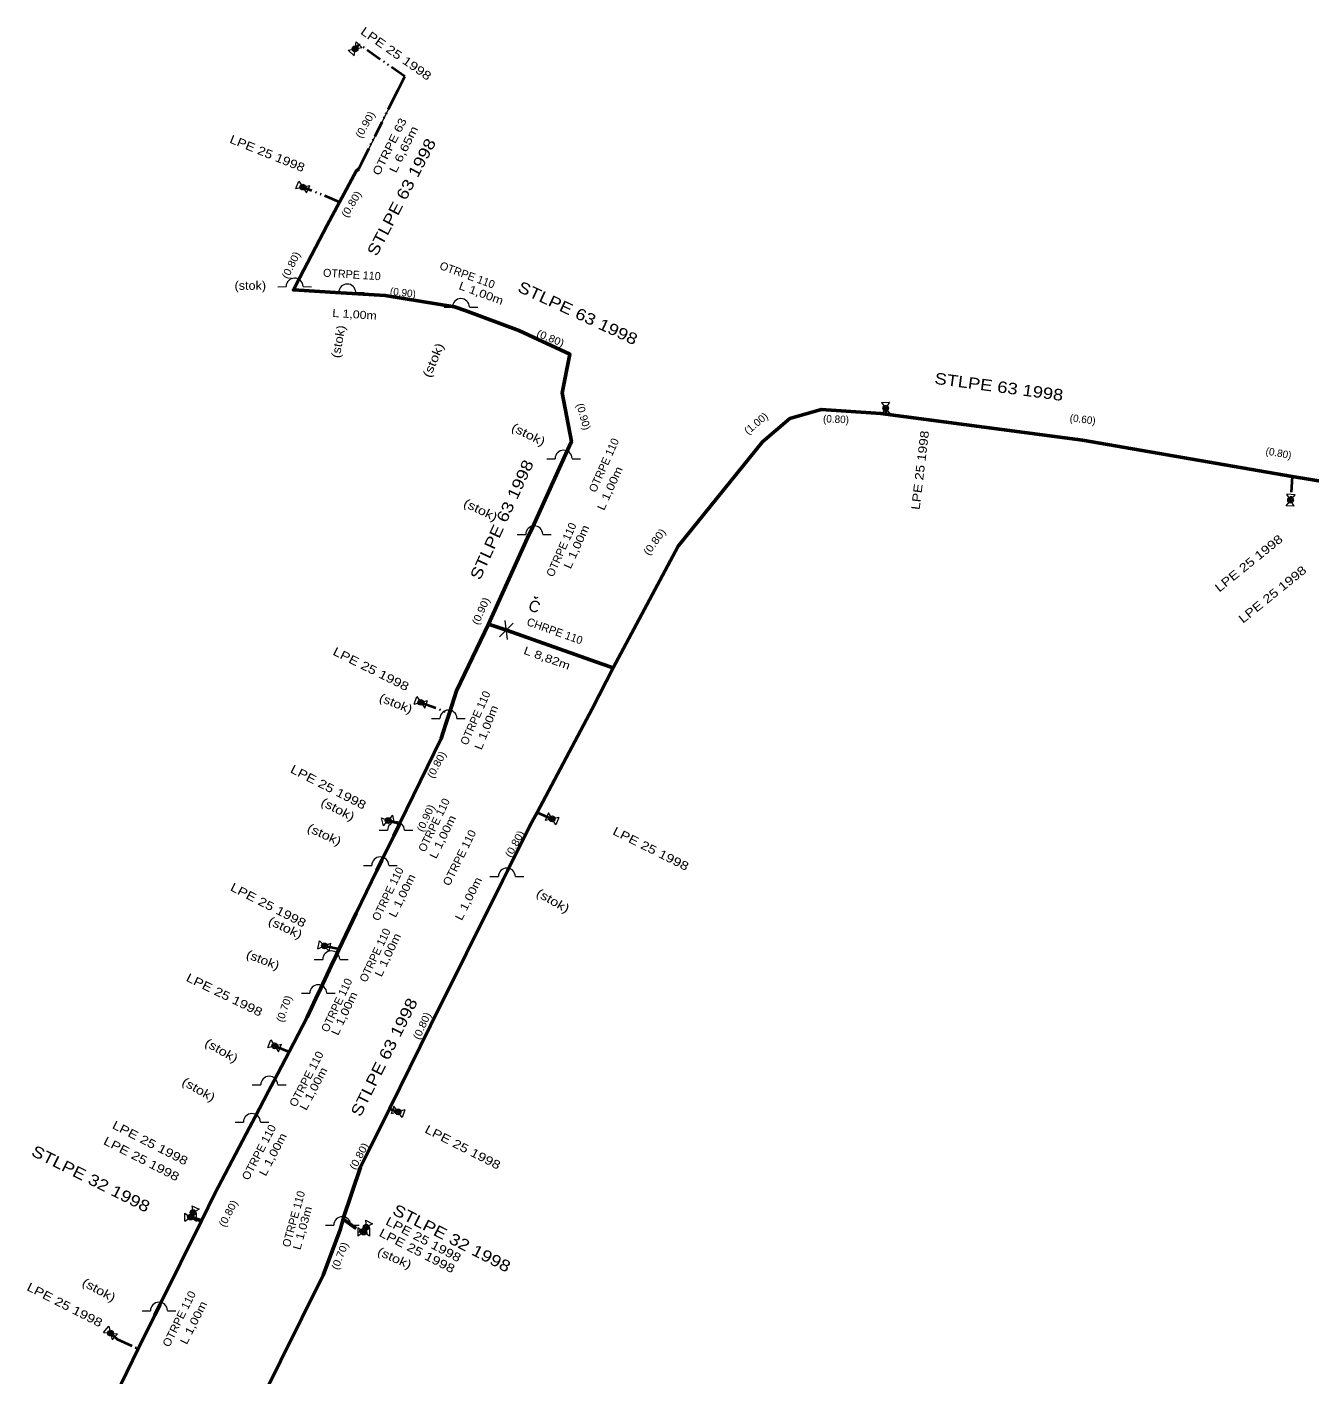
# Model space of a CAD drawing. Extents: x -648036 to -642998, y -1161549 to -1158141.
# Drawn here: x -646651.4 to -646539.3, y -1161084.6 to -1160966.8 of the extents above; entities that cross this region are included whole.
import ezdxf
from ezdxf.enums import TextEntityAlignment as Align

# ---------------------------------------------------------------- set-up
doc = ezdxf.new("R2010")
doc.units = 0
doc.header["$LTSCALE"] = 0.28
doc.linetypes.add('DASH_DOUBLE_DOT', pattern=[9.2, 5, -1.2, 0.3, -1.2, 0.3, -1.2])
for name, color, linetype, lineweight in [('12', 7, 'DASH_DOUBLE_DOT', 40), ('14', 7, 'Continuous', 13), ('15', 7, 'Continuous', 13), ('19', 7, 'Continuous', 13), ('8', 7, 'Continuous', 53)]:
    doc.layers.add(name, color=color, linetype=linetype, lineweight=lineweight)
for name, color, linetype in [('20', 7, 'Continuous'), ('22', 7, 'Continuous'), ('24', 7, 'Continuous'), ('27', 7, 'Continuous'), ('28', 7, 'Continuous')]:
    doc.layers.add(name, color=color, linetype=linetype)

msp = doc.modelspace()

# ---------------------------------------------------------------- linework, layer by layer
at = {"layer": '12'}
for p, q in [((-646624.02, -1160982.11), (-646627.24, -1160980.8)), ((-646576.27, -1161000.14), (-646576.25, -1161000.68)), ((-646540.72, -1161006.11), (-646540.87, -1161008.2)), ((-646616.92, -1161025.88), (-646614.42, -1161026.81)), ((-646606.76, -1161035.51), (-646605.44, -1161036.07)), ((-646625.35, -1161047.19), (-646624.05, -1161047.45)), ((-646629.7, -1161055.93), (-646628.44, -1161056.44)), ((-646619.67, -1161061.45), (-646618.91, -1161061.71)), ((-646637.03, -1161070.91), (-646637.05, -1161070.91)), ((-646637.03, -1161070.91), (-646636.84, -1161070.52)), ((-646621.94, -1161072.22), (-646621.7, -1161071.78)), ((-646621.94, -1161072.22), (-646621.92, -1161072.22))]:
    msp.add_line(p, q, dxfattribs=at)
for points in [[(-646622.35, -1160979.21), (-646622.08, -1160978.67), (-646619.12, -1160972.72), (-646618.93, -1160972.34), (-646618.33, -1160971.13), (-646622.31, -1160968.33), (-646622.67, -1160968.71)], [(-646619.78, -1161036.22), (-646619.65, -1161036.19), (-646618.79, -1161036.52)], [(-646644.05, -1161081.06), (-646643.46, -1161081.58), (-646641.63, -1161082.43)]]:
    msp.add_lwpolyline(points, dxfattribs=at)
at = {"layer": '14'}
for p, q in [((-646619.12, -1160972.72), (-646622.08, -1160978.67)), ((-646627.49, -1160988.72), (-646628.06, -1160989.8)), ((-646623.92, -1160990.05), (-646622.92, -1160990.11)), ((-646613.05, -1160991.61), (-646613.98, -1160991.27)), ((-646604.24, -1161004.13), (-646604.65, -1161005.04)), ((-646607.16, -1161010.57), (-646607.58, -1161011.48)), ((-646609.44, -1161019.56), (-646601.13, -1161022.52)), ((-646614.73, -1161027.76), (-646614.42, -1161026.81)), ((-646619.29, -1161037.55), (-646618.85, -1161036.66)), ((-646620.76, -1161040.58), (-646620.32, -1161039.68)), ((-646609.78, -1161041.5), (-646609.33, -1161040.61)), ((-646624.75, -1161048.94), (-646624.33, -1161048.04)), ((-646626.1, -1161051.79), (-646625.67, -1161050.89)), ((-646629.78, -1161059.01), (-646630.24, -1161059.9)), ((-646631.44, -1161062.19), (-646631.9, -1161063.07)), ((-646623.7, -1161071.03), (-646623.97, -1161072.02)), ((-646640.19, -1161079.5), (-646639.75, -1161078.6))]:
    msp.add_line(p, q, dxfattribs=at)
at = {"layer": '15'}
for p, q in [((-646622.758, -1160969.321), (-646622.582, -1160968.099)), ((-646622.066, -1160968.59), (-646622.582, -1160968.099)), ((-646623.275, -1160968.831), (-646622.066, -1160968.59)), ((-646622.758, -1160969.321), (-646623.275, -1160968.831)), ((-646627.841, -1160980.94), (-646627.573, -1160980.28)), ((-646627.841, -1160980.94), (-646626.639, -1160980.66)), ((-646627.573, -1160980.28), (-646626.908, -1160981.319)), ((-646626.908, -1160981.319), (-646626.639, -1160980.66)), ((-646629.435, -1160989.515), (-646628.7, -1160989.514)), ((-646627.214, -1160989.514), (-646626.48, -1160989.515)), ((-646624.835, -1160990.025), (-646624.1, -1160990.024)), ((-646622.614, -1160990.024), (-646621.88, -1160990.025)), ((-646614.885, -1160991.305), (-646614.15, -1160991.304)), ((-646612.664, -1160991.304), (-646611.93, -1160991.305)), ((-646576.644, -1160999.65), (-646575.933, -1160999.623)), ((-646576.644, -1160999.65), (-646575.896, -1161000.63)), ((-646575.933, -1160999.623), (-646576.607, -1161000.656)), ((-646576.607, -1161000.656), (-646575.896, -1161000.63)), ((-646605.915, -1161004.565), (-646605.18, -1161004.564)), ((-646603.694, -1161004.564), (-646602.96, -1161004.565)), ((-646541.261, -1161008.677), (-646540.479, -1161007.724)), ((-646540.479, -1161007.724), (-646541.189, -1161007.672)), ((-646540.551, -1161008.728), (-646541.189, -1161007.672)), ((-646540.551, -1161008.728), (-646541.261, -1161008.677)), ((-646608.485, -1161011.185), (-646607.75, -1161011.184)), ((-646606.264, -1161011.184), (-646605.53, -1161011.185)), ((-646606.999, -1161016.608), (-646606.904, -1161016.808)), ((-646606.7, -1161016.721), (-646606.904, -1161016.808)), ((-646610.032, -1161020.155), (-646608.849, -1161018.966)), ((-646609.326, -1161020.391), (-646609.555, -1161018.73)), ((-646617.516, -1161026.038), (-646617.268, -1161025.371)), ((-646617.516, -1161026.038), (-646616.324, -1161025.722)), ((-646617.268, -1161025.371), (-646616.573, -1161026.389)), ((-646616.573, -1161026.389), (-646616.324, -1161025.722)), ((-646615.985, -1161027.295), (-646615.25, -1161027.294)), ((-646613.764, -1161027.294), (-646613.03, -1161027.295)), ((-646605.764, -1161035.546), (-646606.043, -1161036.201)), ((-646605.115, -1161036.595), (-646605.764, -1161035.546)), ((-646620.351, -1161035.986), (-646619.21, -1161036.454)), ((-646620.191, -1161036.68), (-646620.351, -1161035.986)), ((-646620.191, -1161036.68), (-646619.369, -1161035.76)), ((-646619.21, -1161036.454), (-646619.369, -1161035.76)), ((-646604.837, -1161035.939), (-646606.043, -1161036.201)), ((-646604.837, -1161035.939), (-646605.115, -1161036.595)), ((-646620.565, -1161037.075), (-646619.83, -1161037.074)), ((-646618.344, -1161037.074), (-646617.61, -1161037.075)), ((-646621.945, -1161040.145), (-646621.21, -1161040.144)), ((-646619.724, -1161040.144), (-646618.99, -1161040.145)), ((-646610.875, -1161041.125), (-646610.14, -1161041.124)), ((-646608.654, -1161041.124), (-646607.92, -1161041.125)), ((-646625.914, -1161047.44), (-646625.774, -1161046.742)), ((-646625.914, -1161047.44), (-646624.786, -1161046.94)), ((-646625.774, -1161046.742), (-646624.927, -1161047.638)), ((-646624.927, -1161047.638), (-646624.786, -1161046.94)), ((-646626.235, -1161048.365), (-646625.5, -1161048.364)), ((-646624.014, -1161048.364), (-646623.28, -1161048.365)), ((-646627.365, -1161051.325), (-646626.63, -1161051.324)), ((-646625.144, -1161051.324), (-646624.41, -1161051.325)), ((-646630.301, -1161056.071), (-646630.034, -1161055.411)), ((-646630.034, -1161055.411), (-646629.367, -1161056.449)), ((-646630.301, -1161056.071), (-646629.099, -1161055.789)), ((-646629.367, -1161056.449), (-646629.099, -1161055.789)), ((-646631.655, -1161059.335), (-646630.92, -1161059.334)), ((-646629.434, -1161059.334), (-646628.7, -1161059.335)), ((-646619.271, -1161061.21), (-646619.502, -1161061.884)), ((-646618.318, -1161061.536), (-646619.502, -1161061.884)), ((-646618.548, -1161062.21), (-646619.271, -1161061.21)), ((-646618.318, -1161061.536), (-646618.548, -1161062.21)), ((-646633.165, -1161062.595), (-646632.43, -1161062.594)), ((-646630.944, -1161062.594), (-646630.21, -1161062.595)), ((-646637.554, -1161071.266), (-646636.546, -1161070.554)), ((-646637.554, -1161070.554), (-646636.547, -1161071.266)), ((-646637.554, -1161071.266), (-646637.554, -1161070.554)), ((-646636.299, -1161070.223), (-646637.38, -1161070.816)), ((-646637.38, -1161070.816), (-646636.741, -1161071.129)), ((-646636.939, -1161069.911), (-646636.741, -1161071.129)), ((-646636.939, -1161069.911), (-646636.299, -1161070.223)), ((-646636.547, -1161071.266), (-646636.546, -1161070.554)), ((-646625.265, -1161071.615), (-646624.53, -1161071.614)), ((-646623.044, -1161071.614), (-646622.31, -1161071.615)), ((-646622.423, -1161071.864), (-646622.424, -1161072.576)), ((-646621.416, -1161071.864), (-646622.424, -1161072.576)), ((-646621.416, -1161072.576), (-646622.423, -1161071.864)), ((-646621.146, -1161071.508), (-646622.253, -1161072.051)), ((-646622.253, -1161072.051), (-646621.629, -1161072.393)), ((-646621.771, -1161071.167), (-646621.629, -1161072.393)), ((-646621.771, -1161071.167), (-646621.146, -1161071.508)), ((-646621.416, -1161071.864), (-646621.416, -1161072.576)), ((-646641.295, -1161079.105), (-646640.56, -1161079.104)), ((-646639.074, -1161079.104), (-646638.34, -1161079.105)), ((-646644.663, -1161080.994), (-646644.193, -1161080.46)), ((-646644.663, -1161080.994), (-646643.437, -1161081.126)), ((-646644.193, -1161080.46), (-646643.908, -1161081.66)), ((-646643.908, -1161081.66), (-646643.437, -1161081.126))]:
    msp.add_line(p, q, dxfattribs=at)
for centre in [(-646627.9574, -1160989.5146), (-646623.3574, -1160990.0246), (-646613.4074, -1160991.3046), (-646604.4374, -1161004.5646), (-646607.0074, -1161011.1846), (-646614.5074, -1161027.2946), (-646619.0874, -1161037.0746), (-646620.4674, -1161040.1446), (-646609.3974, -1161041.1246), (-646624.7574, -1161048.3646), (-646625.8874, -1161051.3246), (-646630.1774, -1161059.3346), (-646631.6874, -1161062.5946), (-646623.7874, -1161071.6146), (-646639.8174, -1161079.1046)]:
    msp.add_arc(centre, 0.7431, 1.2748, 179.83951, dxfattribs=at)
at = {"layer": '19'}
for centre, radius in [((-646622.67, -1160968.71), 0.25), ((-646622.67, -1160968.71), 0.17), ((-646622.67, -1160968.71), 0.09), ((-646627.24, -1160980.8), 0.25), ((-646627.24, -1160980.8), 0.17), ((-646627.24, -1160980.8), 0.09), ((-646576.27, -1161000.14), 0.25), ((-646576.27, -1161000.14), 0.17), ((-646576.27, -1161000.14), 0.09), ((-646540.87, -1161008.2), 0.25), ((-646540.87, -1161008.2), 0.17), ((-646540.87, -1161008.2), 0.09), ((-646616.92, -1161025.88), 0.25), ((-646616.92, -1161025.88), 0.17), ((-646616.92, -1161025.88), 0.09), ((-646619.78, -1161036.22), 0.25), ((-646619.78, -1161036.22), 0.17), ((-646619.78, -1161036.22), 0.09), ((-646605.44, -1161036.07), 0.25), ((-646605.44, -1161036.07), 0.17), ((-646605.44, -1161036.07), 0.09), ((-646625.35, -1161047.19), 0.25), ((-646625.35, -1161047.19), 0.17), ((-646625.35, -1161047.19), 0.09), ((-646629.7, -1161055.93), 0.25), ((-646629.7, -1161055.93), 0.17), ((-646629.7, -1161055.93), 0.09), ((-646618.91, -1161061.71), 0.25), ((-646618.91, -1161061.71), 0.17), ((-646618.91, -1161061.71), 0.09), ((-646637.05, -1161070.91), 0.25), ((-646637.05, -1161070.91), 0.17), ((-646637.05, -1161070.91), 0.09), ((-646636.84, -1161070.52), 0.25), ((-646636.84, -1161070.52), 0.17), ((-646636.84, -1161070.52), 0.09), ((-646621.92, -1161072.22), 0.25), ((-646621.92, -1161072.22), 0.17), ((-646621.92, -1161072.22), 0.09), ((-646621.7, -1161071.78), 0.25), ((-646621.7, -1161071.78), 0.17), ((-646621.7, -1161071.78), 0.09), ((-646644.05, -1161081.06), 0.25), ((-646644.05, -1161081.06), 0.17), ((-646644.05, -1161081.06), 0.09)]:
    msp.add_circle(centre, radius, dxfattribs=at)
at = {"layer": '8', "linetype": 'DASH_DOUBLE_DOT'}
msp.add_line((-646636.11, -1161071.25), (-646637.03, -1161070.91), dxfattribs=at)
at = {"layer": '8'}
for points in [[(-646624.02, -1160982.11), (-646622.56, -1160979.4), (-646622.35, -1160979.21)], [(-646611, -1161019.03), (-646607.58, -1161011.48), (-646607.16, -1161010.57), (-646604.65, -1161005.04), (-646604.24, -1161004.13), (-646603.75, -1161003.05), (-646604.55, -1160998.8), (-646603.88, -1160995.42), (-646608.34, -1160993.35), (-646613.05, -1160991.61), (-646613.98, -1160991.27), (-646620.04, -1160990.29), (-646622.92, -1160990.11), (-646623.92, -1160990.05), (-646628.06, -1160989.8), (-646627.49, -1160988.72), (-646625.1, -1160984.13), (-646624.02, -1160982.11)], [(-646576.25, -1161000.68), (-646576.7, -1161000.62), (-646581.91, -1161000.26), (-646584.64, -1161001.06), (-646587.04, -1161003.08), (-646594.41, -1161012.21), (-646600.1, -1161022.87)], [(-646540.72, -1161006.11), (-646559.06, -1161002.94), (-646576.25, -1161000.68)], [(-646535.69, -1161007.75), (-646537.71, -1161006.63), (-646540.72, -1161006.11)], [(-646611, -1161019.03), (-646613.79, -1161024.87), (-646614.42, -1161026.81)], [(-646609.44, -1161019.56), (-646609.6, -1161019.51), (-646611, -1161019.03)], [(-646600.1, -1161022.87), (-646601.13, -1161022.52), (-646609.44, -1161019.56)], [(-646600.1, -1161022.87), (-646601.94, -1161026.45), (-646606.76, -1161035.51)], [(-646614.42, -1161026.81), (-646614.73, -1161027.76), (-646615.15, -1161029.04), (-646618.79, -1161036.52)], [(-646606.76, -1161035.51), (-646607.35, -1161036.62), (-646609.33, -1161040.61), (-646609.78, -1161041.5), (-646616.08, -1161054.16), (-646619.67, -1161061.45)], [(-646618.79, -1161036.52), (-646618.85, -1161036.66), (-646619.29, -1161037.55), (-646620.32, -1161039.68), (-646620.76, -1161040.58), (-646622.58, -1161044.32), (-646624.05, -1161047.45)], [(-646624.05, -1161047.45), (-646624.33, -1161048.04), (-646624.75, -1161048.94), (-646625.67, -1161050.89), (-646626.1, -1161051.79), (-646626.86, -1161053.42), (-646628.44, -1161056.44)], [(-646628.44, -1161056.44), (-646629.78, -1161059.01), (-646630.24, -1161059.9), (-646631.44, -1161062.19), (-646631.9, -1161063.07), (-646634.92, -1161068.84), (-646636.11, -1161071.25)], [(-646619.67, -1161061.45), (-646622.18, -1161066.54), (-646623.7, -1161071.03), (-646623.72, -1161071.1)], [(-646636.11, -1161071.25), (-646639.75, -1161078.6), (-646640.19, -1161079.5), (-646641.53, -1161082.21), (-646641.63, -1161082.43)], [(-646623.72, -1161071.1), (-646623.97, -1161072.02), (-646625.45, -1161075.99), (-646632.89, -1161090.97), (-646633.34, -1161091.86), (-646634.83, -1161094.87)], [(-646641.63, -1161082.43), (-646646.05, -1161091.49), (-646646.49, -1161092.39), (-646648.35, -1161096.19), (-646650.91, -1161101.13)]]:
    msp.add_lwpolyline(points, dxfattribs=at)
at = {"layer": '8', "linetype": 'DASH_DOUBLE_DOT'}
msp.add_lwpolyline([(-646623.72, -1161071.1), (-646622.31, -1161072.11), (-646621.94, -1161072.22)], dxfattribs=at)

# ---------------------------------------------------------------- texts
at = {"layer": '15'}
msp.add_text('C', height=1, rotation=339.191, dxfattribs=at).set_placement((-646607.1636, -1161017.943), align=Align.CENTER)
at = {"layer": '20', "width": 1.2}
for s, rotation, p in [('STLPE 63 1998', 62.452, (-646618.168, -1160981.9087)), ('STLPE 63 1998', 335.18, (-646603.3994, -1160992.2774)), ('STLPE 63 1998', 352.369, (-646566.4284, -1160998.7623)), ('STLPE 63 1998', 65.317, (-646609.3837, -1161010.1108)), ('STLPE 63 1998', 63.598, (-646619.6808, -1161057.1418)), ('STLPE 32 1998', 333.461, (-646645.9959, -1161068.0071)), ('STLPE 32 1998', 332.888, (-646614.4399, -1161073.1979))]:
    msp.add_text(s, height=1, rotation=rotation, dxfattribs=at).set_placement(p, align=Align.CENTER)
at = {"layer": '22'}
for rotation, width, p in [(324.867, 1.25, (-646619.2983, -1160969.4333)), (338.045, 1.2, (-646630.4782, -1160978.201)), (83.079, 1.2, (-646572.8921, -1161005.6137)), (38.961, 1.25, (-646544.2858, -1161014.0045)), (38.961, 1.25, (-646542.2158, -1161016.7245)), (333.461, 1.25, (-646621.4405, -1161023.2949)), (332.888, 1.25, (-646625.1754, -1161033.6261)), (333.461, 1.25, (-646596.9705, -1161039.0149)), (332.888, 1.25, (-646630.4254, -1161043.9461)), (334.034, 1.25, (-646634.2547, -1161051.8038)), (332.888, 1.25, (-646640.7554, -1161064.7561)), (332.888, 1.25, (-646641.5154, -1161066.1461)), (332.888, 1.25, (-646613.4154, -1161065.1261)), (332.316, 1.25, (-646616.8607, -1161073.1972)), (332.888, 1.25, (-646617.4154, -1161074.1861)), (332.888, 1.25, (-646648.2254, -1161078.9161))]:
    msp.add_text('LPE 25 1998', height=0.75, rotation=rotation, dxfattribs=dict(at, width=width)).set_placement(p, align=Align.CENTER)
at = {"layer": '24'}
for s, rotation, width, p in [('OTRPE 63', 63.598, 1.2, (-646619.3429, -1160977.4166)), ('L 6,65m', 63.598, 1.3, (-646618.1107, -1160977.6621)), ('L 1,00m', 339.764, 1.2, (-646611.7576, -1160990.4104)), ('L 1,00m', 356.38, 1.15, (-646622.7356, -1160992.2817)), ('L 1,00m', 65.89, 1.2, (-646600.071, -1161007.301)), ('L 1,00m', 65.89, 1.2, (-646602.991, -1161012.411)), ('L 8,82m', 340.337, 1.25, (-646606.0018, -1161022.3284)), ('L 1,00m', 68.755, 1.2, (-646610.8789, -1161028.2008)), ('L 1,00m', 64.171, 1.2, (-646614.6946, -1161037.8)), ('OTRPE 110', 63.598, 1.05, (-646613.2274, -1161039.6271)), ('L 1,00m', 64.171, 1.2, (-646618.2446, -1161042.94)), ('L 1,00m', 63.598, 1.2, (-646612.4434, -1161043.2056)), ('L 1,00m', 64.744, 1.2, (-646619.4972, -1161048.1233)), ('L 1,00m', 64.744, 1.2, (-646623.2972, -1161053.2433)), ('OTRPE 110', 62.452, 1.05, (-646626.6147, -1161058.9884)), ('L 1,00m', 62.452, 1.2, (-646625.9984, -1161059.8384)), ('OTRPE 110', 62.452, 1.05, (-646630.7647, -1161065.3984)), ('L 1,00m', 62.452, 1.2, (-646629.5484, -1161065.5884)), ('L 1,03m', 74.485, 1.15, (-646626.9355, -1161071.9581)), ('OTRPE 110', 63.598, 1.05, (-646637.7374, -1161079.9671)), ('L 1,00m', 63.598, 1.2, (-646636.4834, -1161080.3056))]:
    msp.add_text(s, height=0.7, rotation=rotation, dxfattribs=dict(at, width=width)).set_placement(p, align=Align.CENTER)
for s, rotation, p in [('OTRPE 110', 356.38, (-646622.9676, -1160988.795)), ('OTRPE 110', 339.764, (-646612.9726, -1160988.8249)), ('OTRPE 110', 65.89, (-646600.5925, -1161005.2745)), ('OTRPE 110', 65.89, (-646604.3125, -1161012.6645)), ('CHRPE 110', 340.337, (-646605.3188, -1161019.9693)), ('OTRPE 110', 65.89, (-646611.8325, -1161027.3845)), ('OTRPE 110', 64.171, (-646615.4501, -1161036.761)), ('OTRPE 110', 64.171, (-646619.4901, -1161042.791)), ('OTRPE 110', 64.744, (-646620.6105, -1161048.1453)), ('OTRPE 110', 64.744, (-646623.9605, -1161052.5153)), ('OTRPE 110', 74.485, (-646627.7038, -1161071.1671))]:
    msp.add_text(s, height=0.7, rotation=rotation, dxfattribs=at).set_placement(p, align=Align.CENTER)
at = {"layer": '27'}
for s, rotation, width, p in [('(0.90)', 60.161, 1.1, (-646621.5093, -1160975.4987)), ('(0.80)', 59.015, 1.1, (-646622.7223, -1160982.4573)), ('(0.80)', 63.598, 1.1, (-646627.9822, -1160987.775)), ('(0.80)', 337.472, 1.1, (-646605.7075, -1160994.3148)), ('(0.90)', 285.906, 1.05, (-646603.0036, -1161000.9689)), ('(1.00)', 40.107, 1.05, (-646587.3984, -1161001.721)), ('(0.80)', 53.858, 1.15, (-646596.2224, -1161012.0267)), ('(0.90)', 65.89, 1.1, (-646611.3735, -1161018.0223)), ('(0.80)', 61.879, 1.1, (-646615.2554, -1161031.4842)), ('(0.90)', 65.317, 1.1, (-646616.2017, -1161036.1387)), ('(0.80)', 61.306, 1.1, (-646608.4234, -1161038.4205)), ('(0.70)', 70.474, 1.05, (-646628.573, -1161052.7891)), ('(0.80)', 65.317, 1.1, (-646616.5188, -1161054.3152)), ('(0.80)', 61.879, 1.1, (-646622.0454, -1161065.7342)), ('(0.80)', 62.452, 1.1, (-646633.4782, -1161070.7378)), ('(0.70)', 68.182, 1.1, (-646623.6985, -1161074.4253))]:
    msp.add_text(s, height=0.65, rotation=rotation, dxfattribs=dict(at, width=width)).set_placement(p, align=Align.CENTER)
for s, rotation, p in [('(0.90)', 352.942, (-646618.5234, -1160990.352)), ('(0.80)', 357.526, (-646580.628, -1161001.4257)), ('(0.60)', 352.942, (-646559.0789, -1161001.4338)), ('(0.80)', 349.504, (-646541.9702, -1161004.3888))]:
    msp.add_text(s, height=0.65, rotation=rotation, dxfattribs=at).set_placement(p, align=Align.CENTER)
at = {"layer": '28', "width": 1.1}
msp.add_text('(stok)', height=0.75, dxfattribs=at).set_placement((-646631.83, -1160989.79), align=Align.CENTER)
at = {"layer": '28'}
for rotation, width, p in [(79.641, 1.15, (-646623.7617, -1160994.3839)), (67.036, 1.25, (-646615.4834, -1160996.0943)), (333.461, 1.25, (-646607.676, -1161002.776)), (334.034, 1.25, (-646611.8602, -1161009.3806)), (338.045, 1.2, (-646619.2387, -1161026.3191)), (332.888, 1.25, (-646624.3444, -1161035.5612)), (335.18, 1.25, (-646625.5149, -1161037.7814)), (330.024, 1.25, (-646605.5504, -1161043.5584)), (334.607, 1.25, (-646628.9218, -1161045.9256)), (338.618, 1.2, (-646630.8622, -1161048.755)), (330.024, 1.25, (-646634.5404, -1161056.6584)), (330.024, 1.25, (-646636.5304, -1161060.0684)), (335.753, 1.25, (-646619.368, -1161074.8274)), (331.17, 1.25, (-646645.2448, -1161077.6069))]:
    msp.add_text('(stok)', height=0.75, rotation=rotation, dxfattribs=dict(at, width=width)).set_placement(p, align=Align.CENTER)

doc.saveas('drawing.dxf')
